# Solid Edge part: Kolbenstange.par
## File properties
Username: ahadarics
Dokumentum tartalom típus: 0
Author: ahadarics
Last saved by: ahadarics
Revision: 81
Sűrűség: 0,000 kg/m^3
Pontosság: 0,990
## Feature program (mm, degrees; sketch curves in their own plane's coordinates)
base feature "unnamed BaseFeature 1"
sketch for "Furat_1" plane through (0, 0, 24.5) normal (0, 0, 1) x-axis (0, -1, 0)
  hole centre (0, 0) bore radius 3.3235
hole "Furat_1" nominal diameter 8 finite  ThreadDepth = 15 mm
sketch for "Kihúzás_1" plane through (0, 0, -26.9) normal (0, 0, -1) x-axis (0, 1, 0)
  circle centre (0, 0) radius 16
extrude "Kihúzás_1" add finite 15.8 along -normal
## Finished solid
Body 1: solid body, 16 faces, 22 edges, 8 vertices.
  Faces by surface: plane 9, cylinder 4, cone 2, torus 1
  Edges by curve: circle 12, line 6, ellipse 2, intersection 2
Bounding box of the edges (mm; curved faces can reach further): 32.000 x 32.000 x 51.414, from (-16, -16, -26.9) to (16, 16, 24.5137).
Cylindrical faces by radius (mm): R3.32 x1, R3.3235 x1, R6 x1, R16 x1
Conical faces (half-angle, radius in mm at the cone's reference point): 45 deg R3.32 x1, 59 deg R1.6618 x1
Toroidal faces (ring radius, tube radius in mm): R4.8 r1.2 x1
Planar faces by outward normal: +x 1, +z 4, -x 1, -z 1, oblique 2
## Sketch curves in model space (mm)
circle centre (0, 0, -26.9) radius 16
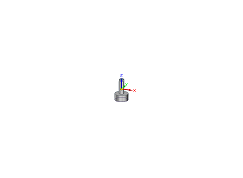
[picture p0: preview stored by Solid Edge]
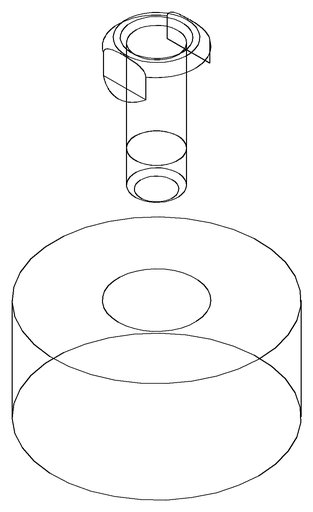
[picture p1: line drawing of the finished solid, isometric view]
